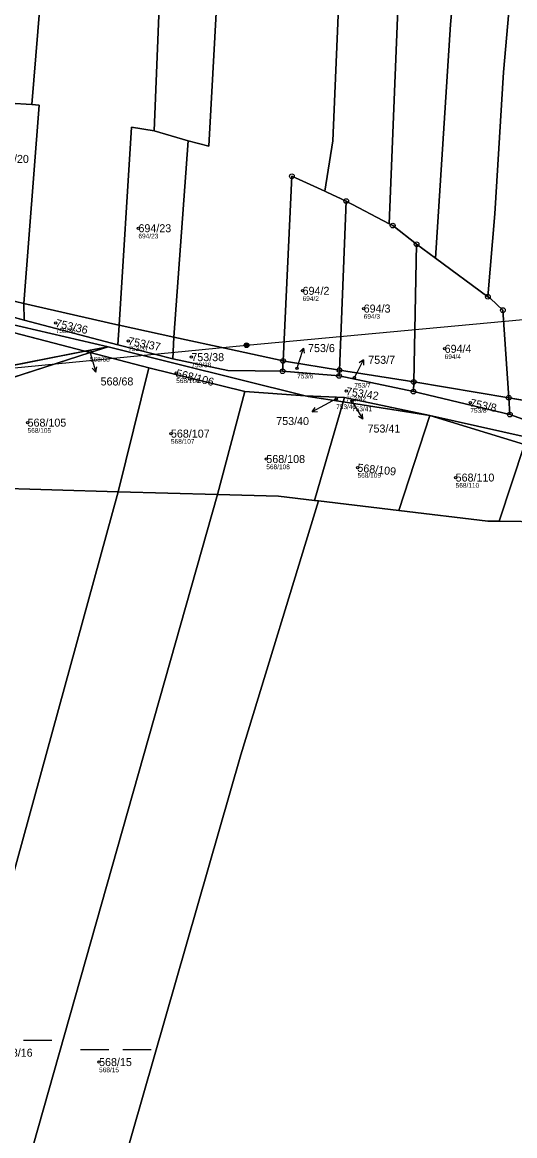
# Model space of a CAD drawing. Extents: x -732749 to -730903, y -1025757 to -1023435.
# Drawn here: x -731612.3 to -731507.8, y -1024340.6 to -1024104.1 of the extents above; entities that cross this region are included whole.
import ezdxf

# ---------------------------------------------------------------- set-up
doc = ezdxf.new("R2010")
doc.units = 0
for name, color, linetype in [('Definiční body', 7, 'Continuous'), ('Hranice parcel', 7, 'Continuous'), ('Parcelní čísla', 7, 'Continuous'), ('Polygon parcely', 7, 'Continuous'), ('Pop  PČ popisy', 7, 'Continuous'), ('Poz předměty', 7, 'Continuous'), ('Značky bodu BP', 7, 'Continuous'), ('Značky kultur', 7, 'Continuous')]:
    doc.layers.add(name, color=color, linetype=linetype)

msp = doc.modelspace()

# ---------------------------------------------------------------- linework, layer by layer
at = {"layer": 'Definiční body'}
for centre in [(-731587.66, -1024147.83), (-731552.81, -1024161.12), (-731539.84, -1024164.89), (-731605.22, -1024167.93), (-731589.8, -1024171.75), (-731522.65, -1024173.44), (-731597.97, -1024174), (-731576.43, -1024175.21), (-731579.65, -1024178.56), (-731553.97, -1024177.57), (-731541.82, -1024179.55), (-731543.56, -1024182.41), (-731545.68, -1024184.09), (-731542.31, -1024184.54), (-731517.2, -1024184.87), (-731611.2, -1024189.12), (-731580.76, -1024191.45), (-731560.51, -1024196.85), (-731541.15, -1024198.66), (-731520.32, -1024200.79), (-731596.02, -1024324.95)]:
    msp.add_circle(centre, 0.25, dxfattribs=at)
at = {"layer": 'Hranice parcel'}
for p, q in [((-731610.3, -1024121.55), (-731619.84, -1024120.95)), ((-731577.09, -1024129.28), (-731584.32, -1024127.17)), ((-731580.16, -1024170.97), (-731577.09, -1024129.28)), ((-731556.97, -1024176.01), (-731555.08, -1024136.77)), ((-731555.08, -1024136.77), (-731548.1, -1024139.92)), ((-731545.01, -1024177.95), (-731543.55, -1024142.05)), ((-731534.4, -1024146.87), (-731543.55, -1024142.05)), ((-731529.23, -1024180.47), (-731528.6, -1024151.22)), ((-731524.59, -1024154.18), (-731528.6, -1024151.22)), ((-731513.48, -1024162.39), (-731524.59, -1024154.18)), ((-731622.71, -1024161.3), (-731611.96, -1024163.79)), ((-731611.89, -1024167.33), (-731611.96, -1024163.79)), ((-731622.99, -1024164.34), (-731611.89, -1024167.33)), ((-731624.08, -1024167.43), (-731599.04, -1024173.96)), ((-731611.89, -1024167.33), (-731592.07, -1024172.58)), ((-731592.07, -1024172.58), (-731591.79, -1024168.44)), ((-731591.79, -1024168.44), (-731580.16, -1024170.97)), ((-731580.37, -1024175.57), (-731580.16, -1024170.97)), ((-731599.04, -1024173.96), (-731594.06, -1024172.99)), ((-731597.94, -1024174.25), (-731594.06, -1024172.99)), ((-731552.26, -1024183.4), (-731594.06, -1024172.99)), ((-731592.07, -1024172.58), (-731580.37, -1024175.57)), ((-731628.41, -1024184.1), (-731597.94, -1024174.25)), ((-731627.2, -1024179.46), (-731599.04, -1024173.96)), ((-731597.94, -1024174.25), (-731599.04, -1024173.96)), ((-731585.47, -1024177.5), (-731597.94, -1024174.25)), ((-731557.07, -1024178.2), (-731556.97, -1024176.01)), ((-731591.95, -1024203.79), (-731585.47, -1024177.5)), ((-731585.47, -1024177.5), (-731565.08, -1024182.52)), ((-731557.07, -1024178.2), (-731545.06, -1024179.19)), ((-731545.06, -1024179.19), (-731545.01, -1024177.95)), ((-731545.01, -1024177.95), (-731529.23, -1024180.47)), ((-731545.06, -1024179.19), (-731529.27, -1024182.51)), ((-731529.27, -1024182.51), (-731529.23, -1024180.47)), ((-731529.23, -1024180.47), (-731509.04, -1024183.85)), ((-731570.87, -1024204.37), (-731565.08, -1024182.52)), ((-731565.08, -1024182.52), (-731552.26, -1024183.4)), ((-731529.27, -1024182.51), (-731508.8, -1024187.4)), ((-731543.89, -1024183.77), (-731552.26, -1024183.4)), ((-731550.27, -1024205.65), (-731544.2, -1024184.72)), ((-731544.2, -1024184.72), (-731543.89, -1024183.77)), ((-731525.78, -1024187.61), (-731544.2, -1024184.72)), ((-731525.78, -1024187.61), (-731543.89, -1024183.77)), ((-731509.04, -1024183.85), (-731498.14, -1024185.69)), ((-731508.8, -1024187.4), (-731509.04, -1024183.85)), ((-731532.41, -1024207.79), (-731525.78, -1024187.61)), ((-731505.72, -1024193.77), (-731525.78, -1024187.61)), ((-731500.21, -1024193.36), (-731525.78, -1024187.61)), ((-731490.35, -1024194.07), (-731508.8, -1024187.4)), ((-731511.09, -1024210.08), (-731505.72, -1024193.77)), ((-731570.87, -1024204.37), (-731591.95, -1024203.79)), ((-731549.41, -1024205.75), (-731550.27, -1024205.65)), ((-731532.41, -1024207.79), (-731549.41, -1024205.75)), ((-731492.29, -1024210.32), (-731511.09, -1024210.08))]:
    msp.add_line(p, q, dxfattribs=at)
for points in [[(-731610.3, -1024121.55), (-731607.78, -1024090.46), (-731607.01, -1024066.74), (-731606.11, -1024057.13), (-731602.02, -1024013.51), (-731601.18, -1024001.14), (-731599.9, -1023986.88)], [(-731584.32, -1024127.17), (-731582.91, -1024092), (-731581.3, -1024059.2), (-731575.22, -1023991.57)], [(-731577.09, -1024129.28), (-731572.74, -1024130.4), (-731569.41, -1024069.88), (-731568.37, -1024054.07), (-731564.88, -1024027.29), (-731562.6, -1024015.52), (-731560.51, -1023997.48), (-731575.22, -1023991.57)], [(-731548.1, -1024139.92), (-731546.39, -1024129.25), (-731544.34, -1024080.82), (-731542.12, -1024057.47), (-731535.98, -1024007.76), (-731522.14, -1024014.05)], [(-731534.4, -1024146.87), (-731532.19, -1024090.75), (-731531.12, -1024079.74), (-731522.14, -1024014.05)], [(-731524.59, -1024154.18), (-731521.42, -1024104.52), (-731518.96, -1024077.33), (-731515.44, -1024047.23), (-731512.29, -1024019.72)], [(-731513.48, -1024162.39), (-731511.99, -1024144.78), (-731510.19, -1024114.67), (-731502.44, -1024027.27)], [(-731611.96, -1024163.79), (-731608.75, -1024121.69), (-731610.3, -1024121.55)], [(-731591.79, -1024168.44), (-731589.13, -1024126.33), (-731584.32, -1024127.17)], [(-731543.55, -1024142.05), (-731547.64, -1024140.13), (-731548.1, -1024139.92)], [(-731528.6, -1024151.22), (-731533.69, -1024147.25), (-731534.4, -1024146.87)], [(-731594.06, -1024172.99), (-731639.82, -1024162.42), (-731656.6, -1024159.72)], [(-731611.96, -1024163.79), (-731592.46, -1024168.3), (-731591.79, -1024168.44)], [(-731509.04, -1024183.85), (-731510.29, -1024165.23), (-731512.95, -1024162.78), (-731513.48, -1024162.39)], [(-731580.16, -1024170.97), (-731568.34, -1024173.54), (-731556.97, -1024176.01)], [(-731580.37, -1024175.57), (-731568.67, -1024178.08), (-731557.07, -1024178.2)], [(-731556.97, -1024176.01), (-731556.26, -1024176.16), (-731545.01, -1024177.95)], [(-731544.2, -1024184.72), (-731551.63, -1024183.56), (-731552.26, -1024183.4)], [(-731591.95, -1024203.79), (-731617.38, -1024296.29), (-731626.82, -1024337.82), (-731646.57, -1024397.91), (-731664.24, -1024469.88)], [(-731570.87, -1024204.37), (-731633.63, -1024425.93), (-731648.93, -1024498.21)], [(-731591.95, -1024203.79), (-731620.23, -1024203), (-731634.3, -1024206.79)], [(-731550.27, -1024205.65), (-731557.95, -1024204.73), (-731570.87, -1024204.37)], [(-731549.41, -1024205.75), (-731565.96, -1024259.66), (-731602.73, -1024388.01), (-731612.84, -1024424.44), (-731631.17, -1024518.71), (-731634.13, -1024529.62)], [(-731511.09, -1024210.08), (-731513.49, -1024210.05), (-731532.41, -1024207.79)]]:
    msp.add_lwpolyline(points, dxfattribs=at)
at = {"layer": 'Polygon parcely'}
for points in [[(-731606.11, -1024057.13), (-731602.02, -1024013.51), (-731601.18, -1024001.14), (-731599.9, -1023986.88), (-731612.57, -1023984.32), (-731614.6, -1024006.74), (-731617.74, -1024035.68), (-731619.63, -1024058.35), (-731620.99, -1024078.89), (-731623.51, -1024120.53), (-731619.84, -1024120.95), (-731610.3, -1024121.55), (-731607.78, -1024090.46), (-731607.01, -1024066.74)], [(-731581.3, -1024059.2), (-731575.22, -1023991.57), (-731596.97, -1023987.47), (-731599.9, -1023986.88), (-731601.18, -1024001.14), (-731602.02, -1024013.51), (-731606.11, -1024057.13), (-731607.01, -1024066.74), (-731607.78, -1024090.46), (-731610.3, -1024121.55), (-731608.75, -1024121.69), (-731611.96, -1024163.79), (-731592.46, -1024168.3), (-731591.79, -1024168.44), (-731589.13, -1024126.33), (-731584.32, -1024127.17), (-731582.91, -1024092)], [(-731564.88, -1024027.29), (-731562.6, -1024015.52), (-731560.51, -1023997.48), (-731575.22, -1023991.57), (-731581.3, -1024059.2), (-731582.91, -1024092), (-731584.32, -1024127.17), (-731577.09, -1024129.28), (-731572.74, -1024130.4), (-731569.41, -1024069.88), (-731568.37, -1024054.07)], [(-731534.4, -1024146.87), (-731532.19, -1024090.75), (-731531.12, -1024079.74), (-731522.14, -1024014.05), (-731535.98, -1024007.76), (-731542.12, -1024057.47), (-731544.34, -1024080.82), (-731546.39, -1024129.25), (-731548.1, -1024139.92), (-731547.64, -1024140.13), (-731543.55, -1024142.05)], [(-731534.4, -1024146.87), (-731533.69, -1024147.25), (-731528.6, -1024151.22), (-731524.59, -1024154.18), (-731521.42, -1024104.52), (-731518.96, -1024077.33), (-731515.44, -1024047.23), (-731512.29, -1024019.72), (-731522.14, -1024014.05), (-731531.12, -1024079.74), (-731532.19, -1024090.75)], [(-731524.59, -1024154.18), (-731513.48, -1024162.39), (-731511.99, -1024144.78), (-731510.19, -1024114.67), (-731502.44, -1024027.27), (-731512.29, -1024019.72), (-731515.44, -1024047.23), (-731518.96, -1024077.33), (-731521.42, -1024104.52)], [(-731509.04, -1024183.85), (-731498.14, -1024185.69), (-731490.27, -1024187.24), (-731489.78, -1024176.64), (-731486.03, -1024140.81), (-731482.41, -1024098.83), (-731479.6, -1024046.51), (-731481.9, -1024043.79), (-731490.81, -1024036.97), (-731502.44, -1024027.27), (-731510.19, -1024114.67), (-731511.99, -1024144.78), (-731513.48, -1024162.39), (-731512.95, -1024162.78), (-731510.29, -1024165.23)], [(-731608.75, -1024121.69), (-731610.3, -1024121.55), (-731619.84, -1024120.95), (-731622.71, -1024161.3), (-731611.96, -1024163.79)], [(-731580.16, -1024170.97), (-731577.09, -1024129.28), (-731584.32, -1024127.17), (-731589.13, -1024126.33), (-731591.79, -1024168.44)], [(-731556.97, -1024176.01), (-731556.26, -1024176.16), (-731545.01, -1024177.95), (-731543.55, -1024142.05), (-731547.64, -1024140.13), (-731548.1, -1024139.92), (-731555.08, -1024136.77)], [(-731534.4, -1024146.87), (-731543.55, -1024142.05), (-731545.01, -1024177.95), (-731529.23, -1024180.47), (-731528.6, -1024151.22), (-731533.69, -1024147.25)], [(-731510.29, -1024165.23), (-731512.95, -1024162.78), (-731513.48, -1024162.39), (-731524.59, -1024154.18), (-731528.6, -1024151.22), (-731529.23, -1024180.47), (-731509.04, -1024183.85)], [(-731594.06, -1024172.99), (-731639.82, -1024162.42), (-731656.6, -1024159.72), (-731657.01, -1024160.85), (-731647.88, -1024162.34), (-731624.08, -1024167.43), (-731599.04, -1024173.96)], [(-731622.99, -1024164.34), (-731611.89, -1024167.33), (-731611.96, -1024163.79), (-731622.71, -1024161.3)], [(-731591.79, -1024168.44), (-731592.46, -1024168.3), (-731611.96, -1024163.79), (-731611.89, -1024167.33), (-731592.07, -1024172.58)], [(-731599.04, -1024173.96), (-731624.08, -1024167.43), (-731627.2, -1024179.46)], [(-731592.07, -1024172.58), (-731580.37, -1024175.57), (-731580.16, -1024170.97), (-731591.79, -1024168.44)], [(-731557.07, -1024178.2), (-731556.97, -1024176.01), (-731568.34, -1024173.54), (-731580.16, -1024170.97), (-731580.37, -1024175.57), (-731568.67, -1024178.08)], [(-731594.06, -1024172.99), (-731599.04, -1024173.96), (-731597.94, -1024174.25)], [(-731565.08, -1024182.52), (-731552.26, -1024183.4), (-731594.06, -1024172.99), (-731597.94, -1024174.25), (-731585.47, -1024177.5)], [(-731585.47, -1024177.5), (-731597.94, -1024174.25), (-731628.41, -1024184.1), (-731634.3, -1024206.79), (-731620.23, -1024203), (-731591.95, -1024203.79)], [(-731597.94, -1024174.25), (-731599.04, -1024173.96), (-731627.2, -1024179.46), (-731628.41, -1024184.1)], [(-731556.97, -1024176.01), (-731557.07, -1024178.2), (-731545.06, -1024179.19), (-731545.01, -1024177.95), (-731556.26, -1024176.16)], [(-731570.87, -1024204.37), (-731565.08, -1024182.52), (-731585.47, -1024177.5), (-731591.95, -1024203.79)], [(-731529.23, -1024180.47), (-731545.01, -1024177.95), (-731545.06, -1024179.19), (-731529.27, -1024182.51)], [(-731529.27, -1024182.51), (-731508.8, -1024187.4), (-731509.04, -1024183.85), (-731529.23, -1024180.47)], [(-731551.63, -1024183.56), (-731552.26, -1024183.4), (-731565.08, -1024182.52), (-731570.87, -1024204.37), (-731557.95, -1024204.73), (-731550.27, -1024205.65), (-731544.2, -1024184.72)], [(-731543.89, -1024183.77), (-731552.26, -1024183.4), (-731551.63, -1024183.56), (-731544.2, -1024184.72)], [(-731532.41, -1024207.79), (-731525.78, -1024187.61), (-731544.2, -1024184.72), (-731550.27, -1024205.65), (-731549.41, -1024205.75)], [(-731543.89, -1024183.77), (-731544.2, -1024184.72), (-731525.78, -1024187.61)], [(-731490.27, -1024187.24), (-731498.14, -1024185.69), (-731509.04, -1024183.85), (-731508.8, -1024187.4), (-731490.35, -1024194.07)], [(-731511.09, -1024210.08), (-731505.72, -1024193.77), (-731525.78, -1024187.61), (-731532.41, -1024207.79), (-731513.49, -1024210.05)], [(-731474.44, -1024197.27), (-731482.49, -1024196.05), (-731500.21, -1024193.36), (-731525.78, -1024187.61), (-731505.72, -1024193.77), (-731488.58, -1024198.66), (-731482.65, -1024200.1)], [(-731488.58, -1024198.66), (-731505.72, -1024193.77), (-731511.09, -1024210.08), (-731492.29, -1024210.32)], [(-731681.24, -1024379.87), (-731681.58, -1024388.61), (-731681, -1024402.03), (-731679.07, -1024434.31), (-731671.48, -1024456.9), (-731664.24, -1024469.88), (-731646.57, -1024397.91), (-731626.82, -1024337.82), (-731617.38, -1024296.29), (-731591.95, -1024203.79), (-731620.23, -1024203), (-731634.3, -1024206.79), (-731645.91, -1024251.08), (-731664.41, -1024328.19), (-731674.52, -1024363.29), (-731680.24, -1024376.54)], [(-731664.24, -1024469.88), (-731650.68, -1024494.17), (-731649.35, -1024497.24), (-731648.93, -1024498.21), (-731633.63, -1024425.93), (-731570.87, -1024204.37), (-731591.95, -1024203.79), (-731617.38, -1024296.29), (-731626.82, -1024337.82), (-731646.57, -1024397.91)], [(-731633.63, -1024425.93), (-731648.93, -1024498.21), (-731638.45, -1024522.46), (-731634.87, -1024528.39), (-731634.13, -1024529.62), (-731631.17, -1024518.71), (-731612.84, -1024424.44), (-731602.73, -1024388.01), (-731565.96, -1024259.66), (-731549.41, -1024205.75), (-731550.27, -1024205.65), (-731557.95, -1024204.73), (-731570.87, -1024204.37)]]:
    msp.add_lwpolyline(points, close=True, dxfattribs=at)
for points in [[(-731500.89, -1024007.04), (-731522.54, -1024002.51), (-731554.18, -1023995.53), (-731558.07, -1023994.8), (-731575.22, -1023991.57), (-731560.51, -1023997.48), (-731562.6, -1024015.52), (-731564.88, -1024027.29), (-731568.37, -1024054.07), (-731569.41, -1024069.88), (-731572.74, -1024130.4), (-731577.09, -1024129.28), (-731580.16, -1024170.97), (-731568.34, -1024173.54), (-731556.97, -1024176.01), (-731555.08, -1024136.77), (-731548.1, -1024139.92), (-731546.39, -1024129.25), (-731544.34, -1024080.82), (-731542.12, -1024057.47), (-731535.98, -1024007.76), (-731522.14, -1024014.05), (-731512.29, -1024019.72), (-731502.44, -1024027.27)], [(-731639.82, -1024162.42), (-731594.06, -1024172.99), (-731552.26, -1024183.4), (-731543.89, -1024183.77), (-731525.78, -1024187.61), (-731500.21, -1024193.36)], [(-731490.35, -1024194.07), (-731508.8, -1024187.4), (-731529.27, -1024182.51), (-731545.06, -1024179.19), (-731557.07, -1024178.2), (-731568.67, -1024178.08), (-731580.37, -1024175.57), (-731592.07, -1024172.58), (-731611.89, -1024167.33), (-731622.99, -1024164.34)], [(-731492.29, -1024210.32), (-731511.09, -1024210.08), (-731513.49, -1024210.05), (-731532.41, -1024207.79), (-731549.41, -1024205.75), (-731565.96, -1024259.66), (-731602.73, -1024388.01)]]:
    msp.add_lwpolyline(points, dxfattribs=at)
at = {"layer": 'Pop  PČ popisy'}
for p, q in [((-731553.53, -1024176.16), (-731552.65, -1024173.29)), ((-731552.65, -1024173.29), (-731553.42, -1024174.1)), ((-731552.65, -1024173.29), (-731552.47, -1024174.39)), ((-731597.97, -1024174), (-731597.53, -1024175.51)), ((-731597.53, -1024175.51), (-731596.7, -1024178.4)), ((-731541.25, -1024178.44), (-731539.89, -1024175.77)), ((-731539.89, -1024175.77), (-731540.79, -1024176.43)), ((-731539.89, -1024175.77), (-731539.9, -1024176.89)), ((-731596.7, -1024178.4), (-731597.46, -1024177.57)), ((-731596.7, -1024178.4), (-731596.5, -1024177.29)), ((-731553.97, -1024177.57), (-731553.53, -1024176.16)), ((-731541.82, -1024179.55), (-731541.25, -1024178.44)), ((-731548.15, -1024185.4), (-731550.8, -1024186.81)), ((-731545.68, -1024184.09), (-731548.15, -1024185.4)), ((-731542.31, -1024184.54), (-731541.55, -1024185.82)), ((-731550.8, -1024186.81), (-731550.15, -1024185.9)), ((-731550.8, -1024186.81), (-731549.68, -1024186.78)), ((-731541.55, -1024185.82), (-731540, -1024188.39)), ((-731540, -1024188.39), (-731540.95, -1024187.79)), ((-731540, -1024188.39), (-731540.09, -1024187.28))]:
    msp.add_line(p, q, dxfattribs=at)
at = {"layer": 'Poz předměty'}
for p, q in [((-731564.72, -1024172.68), (-731502.96, -1024166.91)), ((-731632.07, -1024179.24), (-731564.72, -1024172.68))]:
    msp.add_line(p, q, dxfattribs=at)
for radius in [0.5, 0.4, 0.3, 0.2, 0.1]:
    msp.add_circle((-731564.72, -1024172.68), radius, dxfattribs=at)
at = {"layer": 'Značky bodu BP'}
for centre, radius in [((-731555.08, -1024136.77), 0.5), ((-731555.08, -1024136.77), 0.0303), ((-731543.55, -1024142.05), 0.5), ((-731543.55, -1024142.05), 0.0303), ((-731533.69, -1024147.25), 0.5), ((-731533.69, -1024147.25), 0.0303), ((-731528.6, -1024151.22), 0.5), ((-731528.6, -1024151.22), 0.0303), ((-731513.48, -1024162.39), 0.5), ((-731513.48, -1024162.39), 0.0303), ((-731510.29, -1024165.23), 0.5), ((-731510.29, -1024165.23), 0.0303), ((-731556.97, -1024176.01), 0.5), ((-731556.97, -1024176.01), 0.0303), ((-731557.07, -1024178.2), 0.5), ((-731557.07, -1024178.2), 0.0303), ((-731545.01, -1024177.95), 0.5), ((-731545.01, -1024177.95), 0.0303), ((-731545.06, -1024179.19), 0.5), ((-731545.06, -1024179.19), 0.0303), ((-731529.23, -1024180.47), 0.5), ((-731529.23, -1024180.47), 0.0303), ((-731529.27, -1024182.51), 0.5), ((-731529.27, -1024182.51), 0.0303), ((-731509.04, -1024183.85), 0.5), ((-731509.04, -1024183.85), 0.0303), ((-731508.8, -1024187.4), 0.5), ((-731508.8, -1024187.4), 0.0303)]:
    msp.add_circle(centre, radius, dxfattribs=at)
at = {"layer": 'Značky kultur'}
for p, q in [((-731612.08, -1024320.26), (-731606.08, -1024320.26)), ((-731599.97, -1024322.25), (-731593.97, -1024322.25)), ((-731590.97, -1024322.25), (-731584.97, -1024322.25))]:
    msp.add_line(p, q, dxfattribs=at)

# ---------------------------------------------------------------- texts
at = {"layer": 'Definiční body'}
for s, p in [('694/23', (-731587.66, -1024149.99)), ('694/2', (-731552.81, -1024163.28)), ('694/3', (-731539.84, -1024167.05)), ('753/36', (-731605.22, -1024170.09)), ('753/37', (-731589.8, -1024173.91)), ('568/68', (-731597.97, -1024176.16)), ('694/4', (-731522.65, -1024175.6)), ('753/38', (-731576.43, -1024177.37)), ('568/106', (-731579.65, -1024180.72)), ('753/6', (-731553.97, -1024179.73)), ('753/7', (-731541.82, -1024181.71)), ('753/40', (-731545.68, -1024186.25)), ('753/42', (-731543.56, -1024184.57)), ('753/41', (-731542.31, -1024186.7)), ('753/8', (-731517.2, -1024187.03)), ('568/105', (-731611.2, -1024191.28)), ('568/107', (-731580.76, -1024193.61)), ('568/108', (-731560.51, -1024199.01)), ('568/109', (-731541.15, -1024200.82)), ('568/110', (-731520.32, -1024202.95)), ('568/15', (-731596.02, -1024327.11))]:
    msp.add_text(s, height=1, dxfattribs=at).set_placement(p)
at = {"layer": 'Parcelní čísla'}
for s, p in [('694/20', (-731617.88, -1024133.95)), ('694/23', (-731587.66, -1024148.68)), ('694/2', (-731552.81, -1024161.97)), ('694/3', (-731539.84, -1024165.74)), ('753/6', (-731551.65, -1024174.14)), ('694/4', (-731522.65, -1024174.29)), ('753/38', (-731576.43, -1024176.06)), ('753/7', (-731538.87, -1024176.63)), ('568/68', (-731595.7, -1024181.22)), ('753/40', (-731558.41, -1024189.63)), ('568/105', (-731611.2, -1024189.97)), ('753/41', (-731539.02, -1024191.23)), ('568/107', (-731580.76, -1024192.3)), ('568/108', (-731560.51, -1024197.7)), ('568/110', (-731520.32, -1024201.64)), ('568/16', (-731617.08, -1024323.81)), ('568/15', (-731596.02, -1024325.8))]:
    msp.add_text(s, height=1.7, dxfattribs=at).set_placement(p)
for s, rotation, p in [('753/36', 347, (-731605.41, -1024168.76)), ('753/37', 349, (-731589.96, -1024172.58)), ('568/106', 346, (-731579.85, -1024179.38)), ('753/42', 351, (-731543.69, -1024183.25)), ('753/8', 348, (-731517.38, -1024185.7)), ('568/109', 354, (-731541.24, -1024199.51))]:
    msp.add_text(s, height=1.7, rotation=rotation, dxfattribs=at).set_placement(p)

doc.saveas('drawing.dxf')
